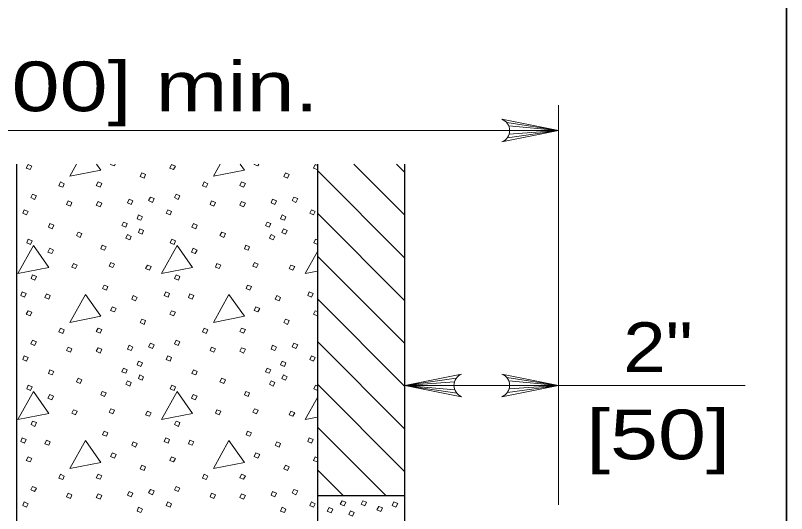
# Model space of a CAD drawing. Extents: x 1083.1 to 1117.1, y 719.4 to 741.4.
# Drawn here: x 1099.648 to 1102.071, y 727.483 to 729.047 of the extents above; entities that cross this region are included whole.
import ezdxf
from ezdxf.enums import TextEntityAlignment as Align

# ---------------------------------------------------------------- set-up
doc = ezdxf.new("R2010")
doc.units = 0
doc.header["$LTSCALE"] = 0.062
doc.layers.add('1', color=7, linetype='Continuous', lineweight=13)

msp = doc.modelspace()

# ---------------------------------------------------------------- linework, layer by layer
at = {"layer": '1', "lineweight": 35}
for q in [(1102.07067, 729.53792), (1102.07067, 724.83408)]:
    msp.add_line((1102.07067, 728.78608), q, dxfattribs=at)
at = {"layer": '1'}
for p, q in [((1101.3545, 727.51033), (1101.3545, 728.76492)), ((1101.19142, 728.71075), (1101.3545, 728.68575)), ((1101.19758, 728.70025), (1101.3545, 728.68575)), ((1098.51258, 728.68575), (1100.9615, 728.68575)), ((1100.9615, 728.68575), (1101.3545, 728.68575)), ((1101.19325, 728.66325), (1101.3545, 728.68575)), ((1101.19875, 728.67442), (1101.3545, 728.68575)), ((1101.20042, 728.68575), (1101.3545, 728.68575)), ((1100.58925, 728.57883), (1100.59642, 728.576)), ((1100.7105, 728.5805), (1100.8715, 728.4195)), ((1100.84483, 728.5805), (1100.8715, 728.55375)), ((1100.59642, 728.56033), (1100.8715, 728.28517)), ((1100.59642, 728.426), (1100.8715, 728.15092)), ((1100.59008, 728.34458), (1100.59642, 728.34208)), ((1100.59642, 728.29175), (1100.8715, 728.01667)), ((1100.59642, 728.1575), (1100.8715, 727.88242)), ((1100.58925, 728.11992), (1100.59642, 728.11708)), ((1100.59642, 728.02325), (1100.8715, 727.74817)), ((1101.03275, 727.90817), (1100.8715, 727.88567)), ((1101.02725, 727.897), (1100.8715, 727.88567)), ((1101.19142, 727.91058), (1101.3545, 727.88567)), ((1101.19758, 727.90008), (1101.3545, 727.88567)), ((1100.59008, 727.88575), (1100.59642, 727.88317)), ((1100.59642, 727.889), (1100.8715, 727.61383)), ((1101.94033, 727.88567), (1100.8715, 727.88567)), ((1101.02558, 727.88567), (1100.8715, 727.88567)), ((1101.02842, 727.87117), (1100.8715, 727.88567)), ((1101.03458, 727.86075), (1100.8715, 727.88567)), ((1101.19325, 727.86308), (1101.3545, 727.88567)), ((1101.19875, 727.87425), (1101.3545, 727.88567)), ((1101.20042, 727.88567), (1101.3545, 727.88567)), ((1100.59642, 727.75467), (1100.81117, 727.54)), ((1100.58925, 727.661), (1100.59642, 727.65817)), ((1100.59642, 727.62042), (1100.67692, 727.54))]:
    msp.add_line(p, q, dxfattribs=at)
at = {"layer": '1', "lineweight": 25}
for p, q in [((1099.65058, 728.5805), (1099.65058, 727.42125)), ((1100.59642, 728.5805), (1100.59642, 727.41542)), ((1100.8715, 727.41542), (1100.8715, 728.5805)), ((1100.59642, 727.54), (1100.8715, 727.54))]:
    msp.add_line(p, q, dxfattribs=at)
at = {"layer": '1'}
for points in [[(1101.17642, 728.72142), (1101.3545, 728.68575), (1101.17642, 728.65017)], [(1099.83983, 728.5805), (1099.81858, 728.54242), (1099.91592, 728.56142), (1099.9025, 728.5805)], [(1099.96142, 728.5805), (1099.95858, 728.57483), (1099.94675, 728.57958), (1099.94717, 728.5805)], [(1100.29083, 728.5805), (1100.26958, 728.54242), (1100.36692, 728.56142), (1100.35358, 728.5805)], [(1100.41242, 728.5805), (1100.40967, 728.57483), (1100.39775, 728.57958), (1100.39817, 728.5805)], [(1100.59642, 728.56458), (1100.59558, 728.563), (1100.58375, 728.56775), (1100.58925, 728.57883)], [(1100.59642, 728.32842), (1100.58533, 728.33358), (1100.59008, 728.34458)], [(1100.59642, 728.30642), (1100.55767, 728.237), (1100.59642, 728.24458)], [(1100.59642, 728.10567), (1100.59558, 728.10408), (1100.58375, 728.10883), (1100.58925, 728.11992)], [(1101.04958, 727.85), (1100.8715, 727.88567), (1101.04958, 727.92125)], [(1101.17642, 727.92125), (1101.3545, 727.88567), (1101.17642, 727.85)], [(1100.59642, 727.8695), (1100.58533, 727.87467), (1100.59008, 727.88575)], [(1100.59642, 727.8475), (1100.55767, 727.77808), (1100.59642, 727.78575)], [(1100.59642, 727.64675), (1100.59558, 727.64517), (1100.58375, 727.64992), (1100.58925, 727.661)]]:
    msp.add_lwpolyline(points, dxfattribs=at)
for points in [[(1099.68717, 728.57883), (1099.69908, 728.57408), (1099.6935, 728.563), (1099.68167, 728.56775)], [(1100.13825, 728.57883), (1100.15008, 728.57408), (1100.14458, 728.563), (1100.13267, 728.56775)], [(1100.04483, 728.55275), (1100.05675, 728.548), (1100.052, 728.53608), (1100.04008, 728.54167)], [(1100.49592, 728.55275), (1100.50775, 728.548), (1100.503, 728.53608), (1100.49117, 728.54167)], [(1099.78925, 728.52425), (1099.80117, 728.51867), (1099.79642, 728.50758), (1099.7845, 728.51233)], [(1099.90717, 728.52425), (1099.91908, 728.5195), (1099.9135, 728.50842), (1099.90167, 728.51317)], [(1100.24033, 728.52425), (1100.25217, 728.51867), (1100.24742, 728.50758), (1100.23558, 728.51233)], [(1100.35825, 728.52425), (1100.37008, 728.5195), (1100.36458, 728.50842), (1100.35267, 728.51317)], [(1099.70142, 728.48625), (1099.71333, 728.48075), (1099.70775, 728.46967), (1099.69592, 728.47517)], [(1100.07175, 728.47675), (1100.08367, 728.472), (1100.07808, 728.46017), (1100.06625, 728.46567)], [(1100.1525, 728.48625), (1100.16433, 728.48075), (1100.15883, 728.46967), (1100.14692, 728.47517)], [(1100.52283, 728.47675), (1100.53467, 728.472), (1100.52917, 728.46017), (1100.51725, 728.46567)], [(1099.813, 728.46492), (1099.82492, 728.45933), (1099.82017, 728.44825), (1099.80825, 728.45383)], [(1099.90717, 728.4625), (1099.91908, 728.45775), (1099.9135, 728.44592), (1099.90167, 728.45142)], [(1100.0045, 728.47042), (1100.01642, 728.46492), (1100.01167, 728.45383), (1099.99975, 728.45858)], [(1100.26408, 728.46492), (1100.27592, 728.45933), (1100.27117, 728.44825), (1100.25933, 728.45383)], [(1100.35825, 728.4625), (1100.37008, 728.45775), (1100.36458, 728.44592), (1100.35267, 728.45142)], [(1100.45558, 728.47042), (1100.46742, 728.46492), (1100.46267, 728.45383), (1100.45083, 728.45858)], [(1099.67533, 728.43717), (1099.68717, 728.43167), (1099.6825, 728.42058), (1099.67058, 728.42608)], [(1100.12633, 728.43717), (1100.13825, 728.43167), (1100.1335, 728.42058), (1100.12167, 728.42608)], [(1100.57742, 728.43717), (1100.58925, 728.43167), (1100.5845, 728.42058), (1100.57267, 728.42608)], [(1100.03458, 728.42058), (1100.04642, 728.415), (1100.04167, 728.404), (1100.02983, 728.40875)], [(1100.48558, 728.42058), (1100.4975, 728.415), (1100.49275, 728.404), (1100.48083, 728.40875)], [(1099.75608, 728.39367), (1099.76792, 728.38817), (1099.76317, 728.37708), (1099.75133, 728.38183)], [(1099.98708, 728.39842), (1099.999, 728.39367), (1099.99425, 728.38258), (1099.98233, 728.38733)], [(1100.03858, 728.37708), (1100.05042, 728.3715), (1100.04567, 728.36042), (1100.03383, 728.366)], [(1100.20708, 728.39367), (1100.21892, 728.38817), (1100.21425, 728.37708), (1100.20233, 728.38183)], [(1100.43817, 728.39842), (1100.45, 728.39367), (1100.44525, 728.38258), (1100.43342, 728.38733)], [(1100.48958, 728.37708), (1100.50142, 728.3715), (1100.49667, 728.36042), (1100.48483, 728.366)], [(1099.84467, 728.36675), (1099.85658, 728.362), (1099.851, 728.35017), (1099.83917, 728.35567)], [(1099.99975, 728.35883), (1100.01167, 728.35333), (1100.00692, 728.34225), (1099.995, 728.34775)], [(1100.29575, 728.36675), (1100.30758, 728.362), (1100.30208, 728.35017), (1100.29017, 728.35567)], [(1100.45083, 728.35883), (1100.46267, 728.35333), (1100.45792, 728.34225), (1100.44608, 728.34775)], [(1099.688, 728.34458), (1099.69983, 728.33983), (1099.69508, 728.328), (1099.68325, 728.33358)], [(1100.139, 728.34458), (1100.15092, 728.33983), (1100.14617, 728.328), (1100.13425, 728.33358)], [(1099.70458, 728.32483), (1099.65558, 728.237), (1099.75292, 728.256)], [(1099.75525, 728.31617), (1099.76717, 728.31058), (1099.76158, 728.2995), (1099.74975, 728.30425)], [(1099.92067, 728.32567), (1099.9325, 728.32092), (1099.92775, 728.30983), (1099.91592, 728.31458)], [(1100.15567, 728.32483), (1100.10658, 728.237), (1100.20392, 728.256)], [(1100.20633, 728.31617), (1100.21817, 728.31058), (1100.21267, 728.2995), (1100.20075, 728.30425)], [(1100.37167, 728.32567), (1100.38358, 728.32092), (1100.37883, 728.30983), (1100.36692, 728.31458)], [(1099.82967, 728.26783), (1099.8415, 728.26317), (1099.83675, 728.25208), (1099.82492, 728.25683)], [(1099.94758, 728.271), (1099.95942, 728.26633), (1099.95383, 728.25525), (1099.942, 728.26)], [(1100.06225, 728.26317), (1100.07417, 728.25842), (1100.06858, 728.24733), (1100.05675, 728.25208)], [(1100.28067, 728.26783), (1100.29258, 728.26317), (1100.28783, 728.25208), (1100.27592, 728.25683)], [(1100.39858, 728.271), (1100.41042, 728.26633), (1100.40492, 728.25525), (1100.39308, 728.26)], [(1100.51333, 728.26317), (1100.52517, 728.25842), (1100.51967, 728.24733), (1100.50775, 728.25208)], [(1099.70142, 728.23225), (1099.71333, 728.2275), (1099.70858, 728.21567), (1099.69667, 728.22117)], [(1100.1525, 728.23225), (1100.16433, 728.2275), (1100.15958, 728.21567), (1100.14775, 728.22117)], [(1099.92617, 728.20058), (1099.93808, 728.19583), (1099.93333, 728.18483), (1099.92142, 728.18958)], [(1100.37725, 728.20058), (1100.38908, 728.19583), (1100.38433, 728.18483), (1100.3725, 728.18958)], [(1099.669, 728.17925), (1099.68092, 728.1745), (1099.67617, 728.16267), (1099.66425, 728.16817)], [(1099.745, 728.17292), (1099.75683, 728.16742), (1099.75208, 728.15633), (1099.74025, 728.16108)], [(1099.86758, 728.17133), (1099.81858, 728.0835), (1099.91592, 728.1025)], [(1100.018, 728.16742), (1100.02983, 728.16183), (1100.02508, 728.15075), (1100.01325, 728.15633)], [(1100.12008, 728.17925), (1100.13192, 728.1745), (1100.12717, 728.16267), (1100.11533, 728.16817)], [(1100.196, 728.17292), (1100.20792, 728.16742), (1100.20317, 728.15633), (1100.19125, 728.16108)], [(1100.31867, 728.17133), (1100.26958, 728.0835), (1100.36692, 728.1025)], [(1100.469, 728.16742), (1100.48083, 728.16183), (1100.47617, 728.15075), (1100.46425, 728.15633)], [(1100.57108, 728.17925), (1100.58292, 728.1745), (1100.57817, 728.16267), (1100.56633, 728.16817)], [(1099.68717, 728.11992), (1099.69908, 728.11517), (1099.6935, 728.10408), (1099.68167, 728.10883)], [(1099.95233, 728.13258), (1099.96417, 728.127), (1099.95858, 728.116), (1099.94675, 728.12075)], [(1100.13825, 728.11992), (1100.15008, 728.11517), (1100.14458, 728.10408), (1100.13267, 728.10883)], [(1100.40333, 728.13258), (1100.41517, 728.127), (1100.40967, 728.116), (1100.39775, 728.12075)], [(1100.04483, 728.09383), (1100.05675, 728.08908), (1100.052, 728.07717), (1100.04008, 728.08275)], [(1100.49592, 728.09383), (1100.50775, 728.08908), (1100.503, 728.07717), (1100.49117, 728.08275)], [(1099.78925, 728.06533), (1099.80117, 728.05975), (1099.79642, 728.04867), (1099.7845, 728.0535)], [(1099.90717, 728.06533), (1099.91908, 728.06058), (1099.9135, 728.0495), (1099.90167, 728.05425)], [(1100.24033, 728.06533), (1100.25217, 728.05975), (1100.24742, 728.04867), (1100.23558, 728.0535)], [(1100.35825, 728.06533), (1100.37008, 728.06058), (1100.36458, 728.0495), (1100.35267, 728.05425)], [(1099.70142, 728.02733), (1099.71333, 728.02183), (1099.70775, 728.01075), (1099.69592, 728.01625)], [(1100.07175, 728.01783), (1100.08367, 728.01308), (1100.07808, 728.00125), (1100.06625, 728.00675)], [(1100.1525, 728.02733), (1100.16433, 728.02183), (1100.15883, 728.01075), (1100.14692, 728.01625)], [(1100.52283, 728.01783), (1100.53467, 728.01308), (1100.52917, 728.00125), (1100.51725, 728.00675)], [(1099.813, 728.006), (1099.82492, 728.00042), (1099.82017, 727.98933), (1099.80825, 727.99492)], [(1099.90717, 728.00358), (1099.91908, 727.99883), (1099.9135, 727.987), (1099.90167, 727.9925)], [(1100.0045, 728.0115), (1100.01642, 728.006), (1100.01167, 727.99492), (1099.99975, 727.99967)], [(1100.26408, 728.006), (1100.27592, 728.00042), (1100.27117, 727.98933), (1100.25933, 727.99492)], [(1100.35825, 728.00358), (1100.37008, 727.99883), (1100.36458, 727.987), (1100.35267, 727.9925)], [(1100.45558, 728.0115), (1100.46742, 728.006), (1100.46267, 727.99492), (1100.45083, 727.99967)], [(1099.67533, 727.97825), (1099.68717, 727.97275), (1099.6825, 727.96167), (1099.67058, 727.96725)], [(1100.12633, 727.97825), (1100.13825, 727.97275), (1100.1335, 727.96167), (1100.12167, 727.96725)], [(1100.57742, 727.97825), (1100.58925, 727.97275), (1100.5845, 727.96167), (1100.57267, 727.96725)], [(1100.03458, 727.96167), (1100.04642, 727.95617), (1100.04167, 727.94508), (1100.02983, 727.94983)], [(1100.48558, 727.96167), (1100.4975, 727.95617), (1100.49275, 727.94508), (1100.48083, 727.94983)], [(1099.75608, 727.93475), (1099.76792, 727.92925), (1099.76317, 727.91817), (1099.75133, 727.92292)], [(1099.98708, 727.9395), (1099.999, 727.93475), (1099.99425, 727.92367), (1099.98233, 727.92842)], [(1100.03858, 727.91817), (1100.05042, 727.91258), (1100.04567, 727.90158), (1100.03383, 727.90708)], [(1100.20708, 727.93475), (1100.21892, 727.92925), (1100.21425, 727.91817), (1100.20233, 727.92292)], [(1100.43817, 727.9395), (1100.45, 727.93475), (1100.44525, 727.92367), (1100.43342, 727.92842)], [(1100.48958, 727.91817), (1100.50142, 727.91258), (1100.49667, 727.90158), (1100.48483, 727.90708)], [(1099.84467, 727.90783), (1099.85658, 727.90317), (1099.851, 727.89125), (1099.83917, 727.89683)], [(1099.99975, 727.9), (1100.01167, 727.89442), (1100.00692, 727.88333), (1099.995, 727.88892)], [(1100.29575, 727.90783), (1100.30758, 727.90317), (1100.30208, 727.89125), (1100.29017, 727.89683)], [(1100.45083, 727.9), (1100.46267, 727.89442), (1100.45792, 727.88333), (1100.44608, 727.88892)], [(1099.688, 727.88575), (1099.69983, 727.881), (1099.69508, 727.86908), (1099.68325, 727.87467)], [(1100.139, 727.88575), (1100.15092, 727.881), (1100.14617, 727.86908), (1100.13425, 727.87467)], [(1099.70458, 727.86592), (1099.65558, 727.77808), (1099.75292, 727.79708)], [(1099.75525, 727.85725), (1099.76717, 727.85167), (1099.76158, 727.84058), (1099.74975, 727.84533)], [(1099.92067, 727.86675), (1099.9325, 727.862), (1099.92775, 727.85092), (1099.91592, 727.85567)], [(1100.15567, 727.86592), (1100.10658, 727.77808), (1100.20392, 727.79708)], [(1100.20633, 727.85725), (1100.21817, 727.85167), (1100.21267, 727.84058), (1100.20075, 727.84533)], [(1100.37167, 727.86675), (1100.38358, 727.862), (1100.37883, 727.85092), (1100.36692, 727.85567)], [(1099.82967, 727.809), (1099.8415, 727.80425), (1099.83675, 727.79317), (1099.82492, 727.79792)], [(1099.94758, 727.81217), (1099.95942, 727.80742), (1099.95383, 727.79633), (1099.942, 727.80108)], [(1100.06225, 727.80425), (1100.07417, 727.7995), (1100.06858, 727.78842), (1100.05675, 727.79317)], [(1100.28067, 727.809), (1100.29258, 727.80425), (1100.28783, 727.79317), (1100.27592, 727.79792)], [(1100.39858, 727.81217), (1100.41042, 727.80742), (1100.40492, 727.79633), (1100.39308, 727.80108)], [(1100.51333, 727.80425), (1100.52517, 727.7995), (1100.51967, 727.78842), (1100.50775, 727.79317)], [(1099.70142, 727.77333), (1099.71333, 727.76858), (1099.70858, 727.75675), (1099.69667, 727.76233)], [(1100.1525, 727.77333), (1100.16433, 727.76858), (1100.15958, 727.75675), (1100.14775, 727.76233)], [(1099.92617, 727.74175), (1099.93808, 727.737), (1099.93333, 727.72592), (1099.92142, 727.73067)], [(1100.37725, 727.74175), (1100.38908, 727.737), (1100.38433, 727.72592), (1100.3725, 727.73067)], [(1099.669, 727.72033), (1099.68092, 727.71558), (1099.67617, 727.70375), (1099.66425, 727.70925)], [(1099.745, 727.714), (1099.75683, 727.7085), (1099.75208, 727.69742), (1099.74025, 727.70217)], [(1099.86758, 727.71242), (1099.81858, 727.62458), (1099.91592, 727.64358)], [(1100.018, 727.7085), (1100.02983, 727.70292), (1100.02508, 727.69183), (1100.01325, 727.69742)], [(1100.12008, 727.72033), (1100.13192, 727.71558), (1100.12717, 727.70375), (1100.11533, 727.70925)], [(1100.196, 727.714), (1100.20792, 727.7085), (1100.20317, 727.69742), (1100.19125, 727.70217)], [(1100.31867, 727.71242), (1100.26958, 727.62458), (1100.36692, 727.64358)], [(1100.469, 727.7085), (1100.48083, 727.70292), (1100.47617, 727.69183), (1100.46425, 727.69742)], [(1100.57108, 727.72033), (1100.58292, 727.71558), (1100.57817, 727.70375), (1100.56633, 727.70925)], [(1099.95233, 727.67367), (1099.96417, 727.66817), (1099.95858, 727.65708), (1099.94675, 727.66183)], [(1100.40333, 727.67367), (1100.41517, 727.66817), (1100.40967, 727.65708), (1100.39775, 727.66183)], [(1099.68717, 727.661), (1099.69908, 727.65625), (1099.6935, 727.64517), (1099.68167, 727.64992)], [(1100.13825, 727.661), (1100.15008, 727.65625), (1100.14458, 727.64517), (1100.13267, 727.64992)], [(1100.04483, 727.63492), (1100.05675, 727.63017), (1100.052, 727.61825), (1100.04008, 727.62383)], [(1100.49592, 727.63492), (1100.50775, 727.63017), (1100.503, 727.61825), (1100.49117, 727.62383)], [(1099.78925, 727.60642), (1099.80117, 727.60092), (1099.79642, 727.58983), (1099.7845, 727.59458)], [(1099.90717, 727.60642), (1099.91908, 727.60167), (1099.9135, 727.59058), (1099.90167, 727.59533)], [(1100.24033, 727.60642), (1100.25217, 727.60092), (1100.24742, 727.58983), (1100.23558, 727.59458)], [(1100.35825, 727.60642), (1100.37008, 727.60167), (1100.36458, 727.59058), (1100.35267, 727.59533)], [(1099.70142, 727.56842), (1099.71333, 727.56292), (1099.70775, 727.55183), (1099.69592, 727.55733)], [(1100.0045, 727.55258), (1100.01642, 727.54708), (1100.01167, 727.536), (1099.99975, 727.54075)], [(1100.07175, 727.55892), (1100.08367, 727.55417), (1100.07808, 727.54233), (1100.06625, 727.54783)], [(1100.1525, 727.56842), (1100.16433, 727.56292), (1100.15883, 727.55183), (1100.14692, 727.55733)], [(1100.45558, 727.55258), (1100.46742, 727.54708), (1100.46267, 727.536), (1100.45083, 727.54075)], [(1100.52283, 727.55892), (1100.53467, 727.55417), (1100.52917, 727.54233), (1100.51725, 727.54783)], [(1099.813, 727.54708), (1099.82492, 727.5415), (1099.82017, 727.5305), (1099.80825, 727.536)], [(1099.90717, 727.54467), (1099.91908, 727.54), (1099.9135, 727.52808), (1099.90167, 727.53367)], [(1100.26408, 727.54708), (1100.27592, 727.5415), (1100.27117, 727.5305), (1100.25933, 727.536)], [(1100.35825, 727.54467), (1100.37008, 727.54), (1100.36458, 727.52808), (1100.35267, 727.53367)], [(1099.67533, 727.51942), (1099.68717, 727.51383), (1099.6825, 727.50275), (1099.67058, 727.50833)], [(1100.12633, 727.51942), (1100.13825, 727.51383), (1100.1335, 727.50275), (1100.12167, 727.50833)], [(1100.57742, 727.51942), (1100.58925, 727.51383), (1100.5845, 727.50275), (1100.57267, 727.50833)], [(1100.67375, 727.52342), (1100.68558, 727.51867), (1100.68008, 727.50683), (1100.66817, 727.51233)], [(1100.73942, 727.52342), (1100.75125, 727.51867), (1100.74575, 727.50683), (1100.73383, 727.51233)], [(1100.78908, 727.50558), (1100.80092, 727.50092), (1100.79542, 727.489), (1100.78358, 727.49458)], [(1100.837, 727.51983), (1100.84892, 727.51508), (1100.84333, 727.50325), (1100.8315, 727.50875)], [(1100.03458, 727.50275), (1100.04642, 727.49725), (1100.04167, 727.48617), (1100.02983, 727.49092)], [(1100.48558, 727.50275), (1100.4975, 727.49725), (1100.49275, 727.48617), (1100.48083, 727.49092)], [(1100.63292, 727.50208), (1100.64475, 727.49733), (1100.63925, 727.48542), (1100.62733, 727.491)], [(1100.70033, 727.4915), (1100.71217, 727.48675), (1100.70667, 727.47483), (1100.69475, 727.48042)]]:
    msp.add_lwpolyline(points, close=True, dxfattribs=at)
for centre, major_axis in [((1101.16197, 728.68579), (0.03843, 0)), ((1101.06403, 727.88564), (-0.03843, 0)), ((1101.16197, 727.88564), (0.03843, 0))]:
    msp.add_ellipse(centre, major_axis=major_axis, ratio=0.999895, start_param=5.0978942, end_param=7.4685073, dxfattribs=at)

# ---------------------------------------------------------------- texts
at = {"layer": '1', "width": 1.3}
msp.add_text('12" [300] min.', height=0.156, dxfattribs=at).set_placement((1098.93617, 728.74642))
at = {"layer": '1'}
for s, width, p in [('2"', 1.15, (1101.66671, 727.9275)), ('[50]', 1.3, (1101.66671, 727.6535))]:
    msp.add_text(s, height=0.156, dxfattribs=dict(at, width=width)).set_placement(p, align=Align.CENTER)

doc.saveas('drawing.dxf')
